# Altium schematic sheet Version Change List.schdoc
size 487 x 190 mm
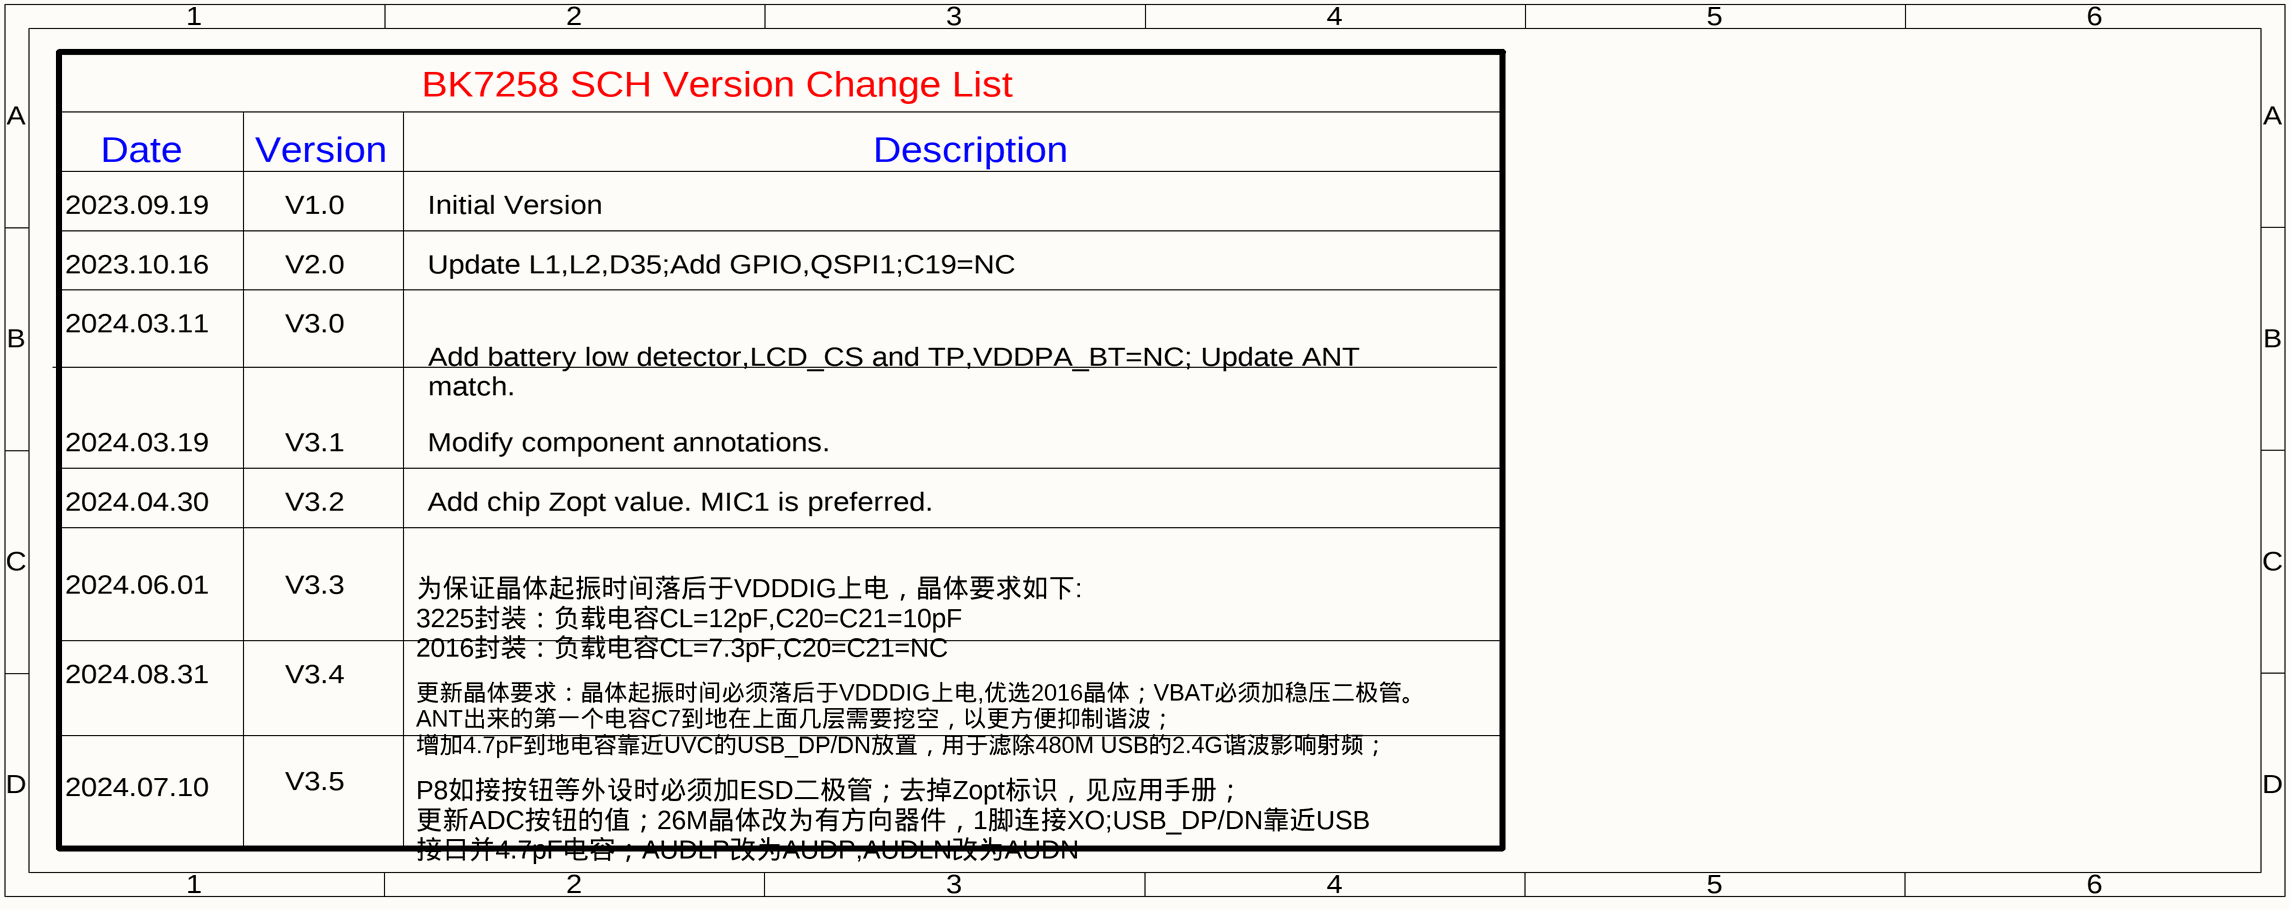
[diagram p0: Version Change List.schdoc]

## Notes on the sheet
- BK7258 SCH Version Change List
- Date
- Version
- Description
- 2023.09.19
- V1.0
- Initial Version
- 2023.10.16
- V2.0
- Update L1,L2,D35;Add GPIO,QSPI1;C19=NC
- 2024.03.11
- V3.0
- Add battery low detector,LCD_CS and TP,VDDPA_BT=NC; Update ANT
  match.
- 2024.03.19
- V3.1
- Modify component annotations.
- 2024.04.30
- V3.2
- Add chip Zopt value. MIC1 is preferred.
- 2024.06.01
- V3.3
- 为保证晶体起振时间落后于VDDDIG上电，晶体要求如下:
  3225封装：负载电容CL=12pF,C20=C21=10pF
  2016封装：负载电容CL=7.3pF,C20=C21=NC
- 更新晶体要求：晶体起振时间必须落后于VDDDIG上电,优选2016晶体；VBAT必须加稳压二极管。
  ANT出来的第一个电容C7到地在上面几层需要挖空，以更方便抑制谐波；
  增加4.7pF到地电容靠近UVC的USB_DP/DN放置，用于滤除480M USB的2.4G谐波影响射频；
- 2024.08.31
- V3.4
- 2024.07.10
- V3.5
- P8如接按钮等外设时必须加ESD二极管；去掉Zopt标识，见应用手册；
  更新ADC按钮的值；26M晶体改为有方向器件，1脚连接XO;USB_DP/DN靠近USB
  接口并4.7pF电容；AUDLP改为AUDP,AUDLN改为AUDN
